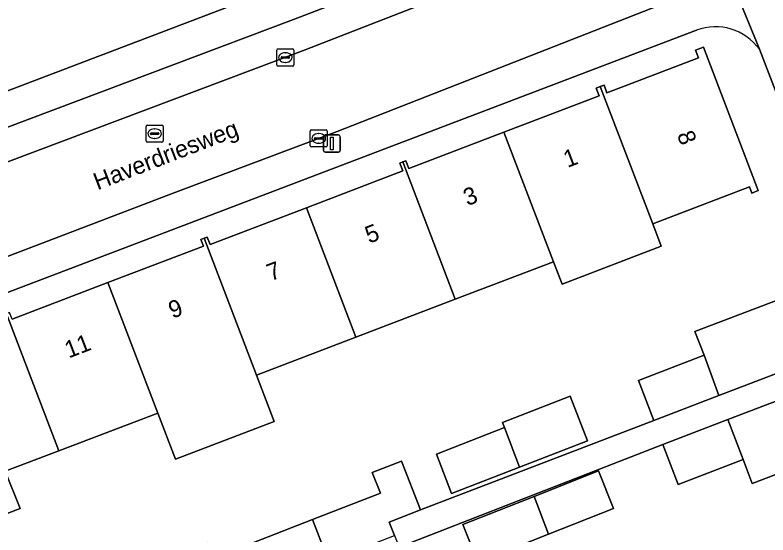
# Model space of a CAD drawing. Extents: x 159262 to 160143, y 383399 to 384319.
# Drawn here: x 159394.93 to 159438.86, y 383819.43 to 383849.77 of the extents above; entities that cross this region are included whole.
import ezdxf

# ---------------------------------------------------------------- set-up
doc = ezdxf.new("R2010")
doc.units = 0
for name, color, linetype in [('IMGEO_Erf', 7, 'Continuous'), ('IMGEO_Kolk', 7, 'Continuous'), ('IMGEO_Lichtmast', 7, 'Continuous'), ('IMGEO_Openbare_ruimte_label', 7, 'Continuous'), ('IMGEO_Pand', 7, 'Continuous'), ('IMGEO_Pand_nummerreeks', 7, 'Continuous'), ('IMGEO_Parkeervlak_open', 7, 'Continuous'), ('IMGEO_Rijbaan_lokaal_open', 7, 'Continuous'), ('IMGEO_Rioolput', 7, 'Continuous'), ('IMGEO_Voetpad_open', 7, 'Continuous')]:
    doc.layers.add(name, color=color, linetype=linetype)

msp = doc.modelspace()

# ---------------------------------------------------------------- linework, layer by layer
at = {"layer": 'IMGEO_Erf'}
for points in [[(159369.194, 383835.764), (159370.416, 383836.226), (159382.457, 383840.783), (159431.75, 383859.554)], [(159434.697, 383848.89), (159387.616, 383830.972), (159374.358, 383825.902), (159370.61, 383824.469)], [(159394.756, 383832.021), (159400.338, 383834.155), (159405.922, 383836.29), (159405.775, 383836.674), (159405.96, 383836.745), (159406.143, 383836.815), (159406.311, 383836.376), (159411.93, 383838.524), (159417.55, 383840.673), (159417.376, 383841.126), (159417.555, 383841.195), (159417.736, 383841.264), (159417.908, 383840.816), (159423.459, 383842.938), (159429.011, 383845.061), (159428.841, 383845.507), (159429.066, 383845.594), (159429.296, 383845.682), (159429.465, 383845.24), (159434.806, 383847.282), (159434.637, 383847.723), (159435.097, 383847.899), (159438.3, 383839.521), (159437.931, 383839.38), (159437.788, 383839.754), (159432.14, 383837.594), (159432.631, 383836.282), (159426.852, 383834.072), (159426.342, 383835.376), (159420.619, 383833.187), (159414.821, 383830.969), (159409.019, 383828.749), (159410.05, 383826.055), (159404.296, 383823.854), (159403.251, 383826.543), (159397.482, 383824.337), (159394.356, 383823.141), (159395.215, 383820.973), (159392.518, 383819.942)], [(159415.776, 383823.077), (159417.47, 383823.737), (159418.581, 383820.888), (159432.195, 383826.114), (159431.303, 383828.45), (159435.133, 383829.914), (159434.603, 383831.296), (159440.581, 383833.581), (159442.002, 383829.864), (159444.835, 383830.954), (159438.361, 383847.773)], [(159450.279, 383816.807), (159446.811, 383825.818), (159443.971, 383824.732), (159437.947, 383822.429), (159437.414, 383823.824), (159433.631, 383822.378), (159432.738, 383824.713), (159417.335, 383818.711), (159417.833, 383817.432), (159414.014, 383815.943), (159410.168, 383814.444), (159409.503, 383816.15), (159382.374, 383805.575), (159383.454, 383802.753), (159384.533, 383799.932), (159385.613, 383797.11), (159386.692, 383794.288), (159387.772, 383791.467), (159388.851, 383788.645), (159382.929, 383786.384), (159382.814, 383786.685), (159376.601, 383784.307)], [(159369.056, 383821.878), (159372.012, 383806.327), (159372.571, 383803.406), (159376.551, 383804.927), (159375.402, 383807.935), (159382.941, 383810.816), (159384.09, 383807.808), (159397.412, 383813.025), (159396.531, 383815.33), (159400.367, 383816.796), (159406.149, 383819.006), (159407.03, 383816.7), (159408.972, 383817.511), (159408.457, 383818.833), (159412.284, 383820.326), (159416.246, 383821.872), (159415.776, 383823.077)]]:
    msp.add_lwpolyline(points, dxfattribs=at)
for points in [[(159423.487, 383825.69), (159423.37, 383825.997), (159427.318, 383827.527), (159428.329, 383824.92), (159424.369, 383823.385), (159420.404, 383821.848), (159419.513, 383824.148)], [(159426.061, 383819.469), (159421.927, 383817.837), (159421.059, 383820.034), (159425.215, 383821.675), (159428.983, 383823.163), (159429.851, 383820.966)]]:
    msp.add_lwpolyline(points, close=True, dxfattribs=at)
msp.add_arc((159435.799, 383845.937), 3.152, 35.6257, 110.4657, dxfattribs=at)
at = {"layer": 'IMGEO_Kolk'}
for p, q in [((159410.199, 383846.864), (159410.199, 383847.716)), ((159410.274, 383847.79), (159411.126, 383847.79)), ((159411.2, 383847.716), (159411.2, 383846.864)), ((159410.458, 383847.284), (159410.458, 383847.296)), ((159410.896, 383847.247), (159410.498, 383847.247)), ((159410.501, 383847.333), (159410.899, 383847.333)), ((159410.687, 383847.57), (159410.712, 383847.57)), ((159410.942, 383847.296), (159410.942, 383847.284)), ((159410.71, 383847.01), (159410.685, 383847.01)), ((159411.126, 383846.79), (159410.274, 383846.79)), ((159412.147, 383842.144), (159412.147, 383842.996)), ((159412.222, 383843.07), (159413.074, 383843.07)), ((159412.635, 383842.85), (159412.66, 383842.85)), ((159413.148, 383842.996), (159413.148, 383842.144)), ((159412.406, 383842.564), (159412.406, 383842.576)), ((159412.844, 383842.527), (159412.446, 383842.527)), ((159412.449, 383842.613), (159412.847, 383842.613)), ((159412.89, 383842.576), (159412.89, 383842.564)), ((159413.074, 383842.07), (159412.222, 383842.07)), ((159412.658, 383842.29), (159412.633, 383842.29))]:
    msp.add_line(p, q, dxfattribs=at)
for points in [[(159410.199, 383846.864), (159410.199, 383847.716)], [(159410.274, 383847.79), (159411.126, 383847.79)], [(159411.2, 383847.716), (159411.2, 383846.864)], [(159411.126, 383846.79), (159410.274, 383846.79)], [(159412.147, 383842.144), (159412.147, 383842.996)], [(159412.222, 383843.07), (159413.074, 383843.07)], [(159413.148, 383842.996), (159413.148, 383842.144)], [(159413.074, 383842.07), (159412.222, 383842.07)]]:
    msp.add_lwpolyline(points, dxfattribs=at)
for centre, radius, start, end in [((159410.276, 383847.714), 0.0765, 91.552, 178.448), ((159410.276, 383847.714), 0.0765, 91.552, 178.448), ((159411.124, 383847.714), 0.0765, 1.552, 88.448), ((159411.124, 383847.714), 0.0765, 1.552, 88.448), ((159410.498, 383847.293), 0.0403, 85.8775, 175.7526), ((159410.495, 383847.283), 0.0366, 178.938, 274.7102), ((159410.899, 383847.29), 0.043, 264.8664, 352.4533), ((159410.903, 383847.295), 0.0386, 1.7309, 96.639), ((159410.276, 383846.866), 0.0765, 181.552, 268.448), ((159410.276, 383846.866), 0.0765, 181.552, 268.448), ((159411.124, 383846.866), 0.0765, 271.552, 358.448), ((159411.124, 383846.866), 0.0765, 271.552, 358.448), ((159412.224, 383842.994), 0.0765, 91.552, 178.448), ((159412.224, 383842.994), 0.0765, 91.552, 178.448), ((159413.072, 383842.994), 0.0765, 1.552, 88.448), ((159413.072, 383842.994), 0.0765, 1.552, 88.448), ((159412.446, 383842.573), 0.0403, 85.8775, 175.7526), ((159412.443, 383842.563), 0.0366, 178.938, 274.7102), ((159412.847, 383842.57), 0.043, 264.8664, 352.4533), ((159412.851, 383842.575), 0.0386, 1.7309, 96.639), ((159412.224, 383842.146), 0.0765, 181.552, 268.448), ((159412.224, 383842.146), 0.0765, 181.552, 268.448), ((159413.072, 383842.146), 0.0765, 271.552, 358.448), ((159413.072, 383842.146), 0.0765, 271.552, 358.448)]:
    msp.add_arc(centre, radius, start, end, dxfattribs=at)
for centre, major_axis, ratio, start_param, end_param in [((159410.686, 383847.29), (-0.387, 0.002), 0.722429, 4.712389, 7.853982), ((159410.711, 383847.29), (-0.39, 0.002), 0.717154, 1.570796, 4.712389), ((159412.634, 383842.57), (-0.387, 0.002), 0.722429, 4.712389, 7.853982), ((159412.659, 383842.57), (-0.39, 0.002), 0.717154, 1.570796, 4.712389)]:
    msp.add_ellipse(centre, major_axis=major_axis, ratio=ratio, start_param=start_param, end_param=end_param, dxfattribs=at)
at = {"layer": 'IMGEO_Lichtmast'}
for p, q in [((159412.918, 383841.87), (159412.918, 383842.67)), ((159412.918, 383842.67), (159412.918, 383841.87)), ((159413.018, 383842.77), (159413.808, 383842.77)), ((159413.808, 383842.77), (159413.018, 383842.77)), ((159413.908, 383842.67), (159413.908, 383841.87)), ((159413.908, 383841.87), (159413.908, 383842.67)), ((159413.808, 383841.77), (159413.018, 383841.77)), ((159413.018, 383841.77), (159413.808, 383841.77))]:
    msp.add_line(p, q, dxfattribs=at)
msp.add_lwpolyline([(159413.338, 383842.645), (159413.488, 383842.645), (159413.488, 383841.895), (159413.338, 383841.895), (159413.338, 383842.645)], dxfattribs=at)
for centre, start, end in [((159413.018, 383842.67), 90, 180), ((159413.018, 383842.67), 90, 180), ((159413.808, 383842.67), 0, 90), ((159413.808, 383842.67), 360, 90), ((159413.018, 383841.87), 180, 270), ((159413.018, 383841.87), 180, 270), ((159413.808, 383841.87), 270, 0), ((159413.808, 383841.87), 270, 0)]:
    msp.add_arc(centre, 0.1, start, end, dxfattribs=at)
at = {"layer": 'IMGEO_Pand'}
for points in [[(159432.14, 383837.594), (159437.788, 383839.754), (159437.931, 383839.38), (159438.3, 383839.521), (159435.097, 383847.899), (159434.637, 383847.723), (159434.806, 383847.282), (159429.465, 383845.24), (159429.296, 383845.682), (159429.066, 383845.594)], [(159423.459, 383842.938), (159426.342, 383835.376), (159426.852, 383834.072), (159432.631, 383836.282), (159432.14, 383837.594), (159429.066, 383845.594), (159428.841, 383845.507), (159429.011, 383845.061)], [(159423.459, 383842.938), (159417.908, 383840.816), (159417.736, 383841.264), (159417.555, 383841.195), (159420.619, 383833.187), (159426.342, 383835.376)], [(159411.93, 383838.524), (159414.821, 383830.969), (159420.619, 383833.187), (159417.555, 383841.195), (159417.376, 383841.126), (159417.55, 383840.673)], [(159411.93, 383838.524), (159406.311, 383836.376), (159406.143, 383836.815), (159405.96, 383836.745), (159409.019, 383828.749), (159414.821, 383830.969)], [(159403.251, 383826.543), (159404.296, 383823.854), (159410.05, 383826.055), (159409.019, 383828.749), (159405.96, 383836.745), (159405.775, 383836.674), (159405.922, 383836.29), (159400.338, 383834.155)], [(159397.482, 383824.337), (159403.251, 383826.543), (159400.338, 383834.155), (159394.756, 383832.021), (159394.607, 383832.411), (159394.42, 383832.34)], [(159435.133, 383829.914), (159436.005, 383827.571), (159442.002, 383829.864), (159440.581, 383833.581), (159434.603, 383831.296)], [(159397.482, 383824.337), (159394.42, 383832.34), (159394.237, 383832.27), (159394.394, 383831.86), (159388.779, 383829.713), (159392.518, 383819.942), (159395.215, 383820.973), (159394.356, 383823.141)], [(159435.133, 383829.914), (159431.303, 383828.45), (159432.195, 383826.114), (159436.005, 383827.571)], [(159436.527, 383826.162), (159437.414, 383823.824), (159437.947, 383822.429), (159443.971, 383824.732), (159446.811, 383825.818), (159445.377, 383829.545), (159442.545, 383828.462)], [(159427.318, 383827.527), (159423.37, 383825.997), (159423.487, 383825.69), (159424.369, 383823.385), (159428.329, 383824.92)], [(159436.527, 383826.162), (159432.738, 383824.713), (159433.631, 383822.378), (159437.414, 383823.824)], [(159423.487, 383825.69), (159419.513, 383824.148), (159420.404, 383821.848), (159424.369, 383823.385)], [(159418.581, 383820.888), (159417.47, 383823.737), (159415.776, 383823.077), (159416.246, 383821.872), (159412.284, 383820.326), (159413.225, 383817.899), (159417.072, 383819.385), (159416.763, 383820.179)], [(159425.215, 383821.675), (159426.061, 383819.469), (159429.851, 383820.966), (159428.983, 383823.163)], [(159425.215, 383821.675), (159421.059, 383820.034), (159421.927, 383817.837), (159426.061, 383819.469)], [(159412.284, 383820.326), (159408.457, 383818.833), (159408.972, 383817.511), (159409.397, 383816.422), (159413.225, 383817.899)]]:
    msp.add_lwpolyline(points, close=True, dxfattribs=at)
at = {"layer": 'IMGEO_Parkeervlak_open'}
for points in [[(159427.802, 383855.889), (159411.178, 383849.519), (159383.074, 383838.931), (159374.2, 383835.498)], [(159371.844, 383832.486), (159383.623, 383837.11), (159411.861, 383847.734), (159430.92, 383855.178)]]:
    msp.add_lwpolyline(points, dxfattribs=at)
at = {"layer": 'IMGEO_Rijbaan_lokaal_open'}
msp.add_lwpolyline([(159432.041, 383850.161), (159432.689, 383850.402), (159433.465, 383850.712), (159431.695, 383855.47), (159431.498, 383855.404), (159431.28, 383855.319), (159430.92, 383855.178), (159411.861, 383847.734), (159383.623, 383837.11), (159371.844, 383832.486), (159373.65, 383827.758), (159377.676, 383829.295), (159387.324, 383832.951), (159404.16, 383839.368), (159413.728, 383842.98)], close=True, dxfattribs=at)
msp.add_arc((159436.146, 383845.487), 5.835, 18.2234, 82.1631, dxfattribs=at)
at = {"layer": 'IMGEO_Rioolput'}
for p, q in [((159402.648, 383843.349), (159403.5, 383843.349)), ((159402.573, 383842.423), (159402.573, 383843.275)), ((159402.832, 383842.843), (159402.832, 383842.855)), ((159402.875, 383842.892), (159403.273, 383842.892)), ((159403.061, 383843.129), (159403.086, 383843.129)), ((159403.316, 383842.855), (159403.316, 383842.843)), ((159403.574, 383843.275), (159403.574, 383842.423)), ((159403.27, 383842.806), (159402.872, 383842.806)), ((159403.084, 383842.569), (159403.059, 383842.569)), ((159403.5, 383842.349), (159402.648, 383842.349))]:
    msp.add_line(p, q, dxfattribs=at)
for points in [[(159402.648, 383843.349), (159403.5, 383843.349)], [(159402.573, 383842.423), (159402.573, 383843.275)], [(159403.574, 383843.275), (159403.574, 383842.423)], [(159403.5, 383842.349), (159402.648, 383842.349)]]:
    msp.add_lwpolyline(points, dxfattribs=at)
for centre, radius, start, end in [((159402.65, 383843.273), 0.0765, 91.552, 178.448), ((159402.65, 383843.273), 0.0765, 91.552, 178.448), ((159403.498, 383843.273), 0.0765, 1.552, 88.448), ((159403.498, 383843.273), 0.0765, 1.552, 88.448), ((159402.872, 383842.852), 0.0403, 85.8775, 175.7526), ((159403.277, 383842.854), 0.0386, 1.7309, 96.639), ((159402.65, 383842.425), 0.0765, 181.552, 268.448), ((159402.65, 383842.425), 0.0765, 181.552, 268.448), ((159402.869, 383842.842), 0.0366, 178.938, 274.7102), ((159403.273, 383842.849), 0.043, 264.8664, 352.4533), ((159403.498, 383842.425), 0.0765, 271.552, 358.448), ((159403.498, 383842.425), 0.0765, 271.552, 358.448)]:
    msp.add_arc(centre, radius, start, end, dxfattribs=at)
for centre, major_axis, ratio, start_param, end_param in [((159403.06, 383842.849), (-0.387, 0.002), 0.722429, 4.712389, 7.853982), ((159403.085, 383842.849), (-0.39, 0.002), 0.717154, 1.570796, 4.712389)]:
    msp.add_ellipse(centre, major_axis=major_axis, ratio=ratio, start_param=start_param, end_param=end_param, dxfattribs=at)
at = {"layer": 'IMGEO_Voetpad_open'}
for points in [[(159431.75, 383859.554), (159382.457, 383840.783), (159370.416, 383836.226), (159371.844, 383832.486)], [(159374.2, 383835.498), (159383.074, 383838.931), (159411.178, 383849.519), (159427.802, 383855.889)], [(159438.361, 383847.773), (159436.942, 383851.268)], [(159436.942, 383851.268), (159438.361, 383847.773), (159444.835, 383830.954), (159445.377, 383829.545), (159446.811, 383825.818), (159450.279, 383816.807), (159453.011, 383809.711), (159453.039, 383809.632), (159455.084, 383804.175), (159456.91, 383799.271), (159457.253, 383798.289), (159458.547, 383794.996)], [(159434.05, 383850.932), (159433.465, 383850.712), (159432.689, 383850.402), (159432.041, 383850.161), (159413.728, 383842.98), (159404.16, 383839.368), (159387.324, 383832.951), (159377.676, 383829.295), (159373.65, 383827.758), (159374.358, 383825.902), (159387.616, 383830.972)], [(159387.616, 383830.972), (159434.697, 383848.89)]]:
    msp.add_lwpolyline(points, dxfattribs=at)
msp.add_lwpolyline([(159432.738, 383824.713), (159436.527, 383826.162), (159442.545, 383828.462), (159445.377, 383829.545), (159444.835, 383830.954), (159442.002, 383829.864), (159436.005, 383827.571), (159432.195, 383826.114), (159418.581, 383820.888), (159416.763, 383820.179), (159417.072, 383819.385), (159417.335, 383818.711)], close=True, dxfattribs=at)
for centre, radius, start, end in [((159436.146, 383845.487), 5.835, 18.2234, 82.1631), ((159435.799, 383845.937), 3.152, 35.6257, 110.4657)]:
    msp.add_arc(centre, radius, start, end, dxfattribs=at)

# ---------------------------------------------------------------- texts
at = {"layer": 'IMGEO_Openbare_ruimte_label'}
msp.add_text('Haverdriesweg', height=1, rotation=21.0992, dxfattribs=at).set_placement((159399.739, 383839.538))
at = {"layer": 'IMGEO_Pand_nummerreeks'}
for s, rotation, p in [('8', 290.9224, (159433.538, 383842.792)), ('1', 20.9052, (159427.163, 383840.845)), ('3', 20.9052, (159421.321, 383838.613)), ('5', 20.9052, (159415.586, 383836.422)), ('7', 20.9052, (159409.85, 383834.231)), ('9', 20.9052, (159404.115, 383832.041)), ('11', 20.9052, (159398.057, 383829.726))]:
    msp.add_text(s, height=1, rotation=rotation, dxfattribs=at).set_placement(p)

doc.saveas('drawing.dxf')
